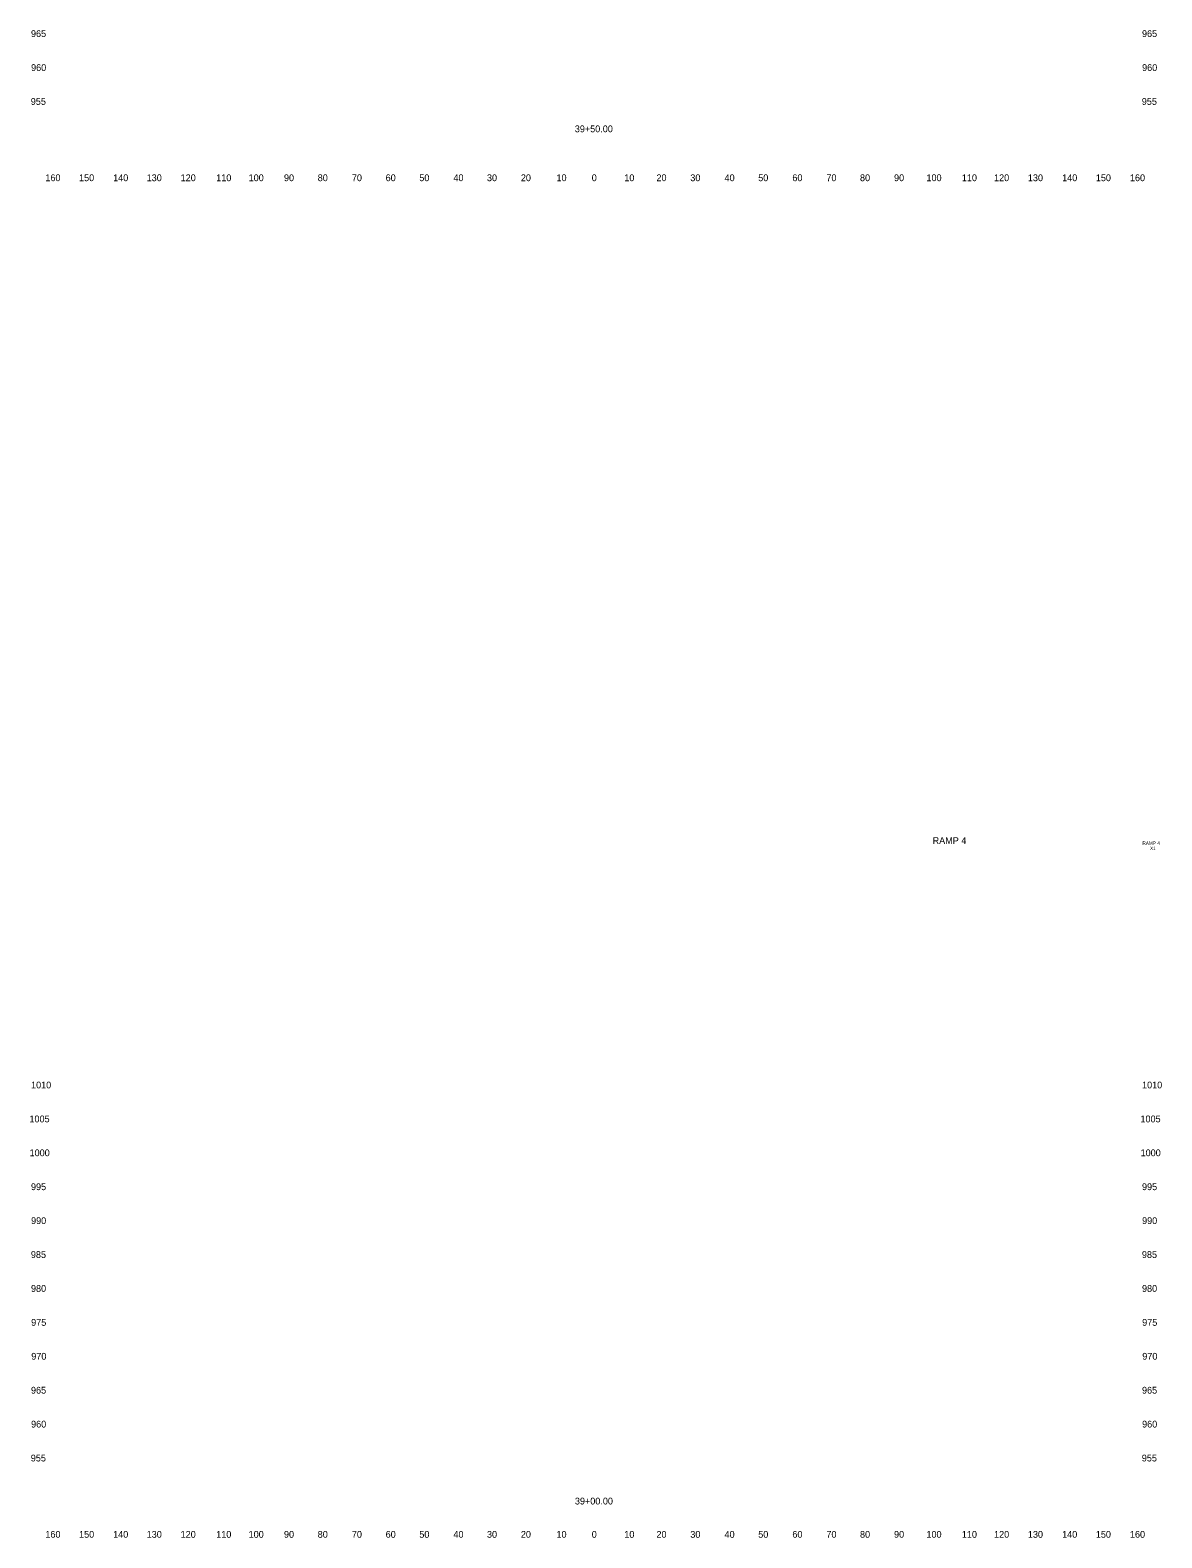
# Model space of a CAD drawing. Extents: x 4994 to 6872, y 4997 to 8804.
# Drawn here: x 4993.6 to 5327.5, y 4997.5 to 5442 of the extents above; entities that cross this region are included whole.
import ezdxf

# ---------------------------------------------------------------- set-up
doc = ezdxf.new("R2010")
doc.units = 0
for name, color, linetype in [('RD_SHT_ID', 7, 'Continuous'), ('RD_XS_TX_Offset', 7, 'Continuous'), ('RD_XS_TX_Station', 7, 'Continuous')]:
    doc.layers.add(name, color=color, linetype=linetype)

msp = doc.modelspace()

# ---------------------------------------------------------------- texts
at = {"layer": 'RD_SHT_ID'}
for s, height, p in [('RAMP 4', 2, (5259.88, 5202.06)), ('RAMP 4', 1, (5321.78, 5201.8)), ('X1', 1, (5324.02, 5200.3))]:
    msp.add_text(s, height=height, dxfattribs=at).set_placement(p)
at = {"layer": 'RD_XS_TX_Offset'}
for s, p in [('965', (4993.86, 5440)), ('965', (5321.66, 5440)), ('960', (4993.89, 5430)), ('960', (5321.69, 5430)), ('955', (4993.8, 5420)), ('955', (5321.6, 5420)), ('160', (4998.1, 5397.5)), ('150', (5008.04, 5397.5)), ('140', (5018.1, 5397.5)), ('130', (5027.99, 5397.5)), ('120', (5038.01, 5397.5)), ('110', (5048.51, 5397.5)), ('100', (5058.07, 5397.5)), ('90', (5068.5, 5397.5)), ('80', (5078.46, 5397.5)), ('70', (5088.54, 5397.5)), ('60', (5098.5, 5397.5)), ('50', (5108.43, 5397.5)), ('40', (5118.5, 5397.5)), ('30', (5128.39, 5397.5)), ('20', (5138.4, 5397.5)), ('10', (5148.91, 5397.5)), ('0', (5159.3, 5397.5)), ('0', (5159.3, 5397.5)), ('10', (5168.91, 5397.5)), ('20', (5178.4, 5397.5)), ('30', (5188.39, 5397.5)), ('40', (5198.5, 5397.5)), ('50', (5208.43, 5397.5)), ('60', (5218.5, 5397.5)), ('70', (5228.54, 5397.5)), ('80', (5238.46, 5397.5)), ('90', (5248.5, 5397.5)), ('100', (5258.07, 5397.5)), ('110', (5268.51, 5397.5)), ('120', (5278.01, 5397.5)), ('130', (5287.99, 5397.5)), ('140', (5298.1, 5397.5)), ('150', (5308.04, 5397.5)), ('160', (5318.1, 5397.5)), ('1010', (4993.88, 5130)), ('1010', (5321.68, 5130)), ('1005', (4993.4, 5120)), ('1005', (5321.2, 5120)), ('1000', (4993.44, 5110)), ('1000', (5321.24, 5110)), ('995', (4993.86, 5100)), ('995', (5321.66, 5100)), ('990', (4993.89, 5090)), ('990', (5321.69, 5090)), ('985', (4993.83, 5080)), ('985', (5321.63, 5080)), ('980', (4993.86, 5070)), ('980', (5321.66, 5070)), ('975', (4993.91, 5060)), ('975', (5321.71, 5060)), ('970', (4993.94, 5050)), ('970', (5321.74, 5050)), ('965', (4993.86, 5040)), ('965', (5321.66, 5040)), ('960', (4993.89, 5030)), ('960', (5321.69, 5030)), ('955', (4993.8, 5020)), ('955', (5321.6, 5020)), ('160', (4998.1, 4997.5)), ('150', (5008.04, 4997.5)), ('140', (5018.1, 4997.5)), ('130', (5027.99, 4997.5)), ('120', (5038.01, 4997.5)), ('110', (5048.51, 4997.5)), ('100', (5058.07, 4997.5)), ('90', (5068.5, 4997.5)), ('80', (5078.46, 4997.5)), ('70', (5088.54, 4997.5)), ('60', (5098.5, 4997.5)), ('50', (5108.43, 4997.5)), ('40', (5118.5, 4997.5)), ('30', (5128.39, 4997.5)), ('20', (5138.4, 4997.5)), ('10', (5148.91, 4997.5)), ('0', (5159.3, 4997.5)), ('0', (5159.3, 4997.5)), ('10', (5168.91, 4997.5)), ('20', (5178.4, 4997.5)), ('30', (5188.39, 4997.5)), ('40', (5198.5, 4997.5)), ('50', (5208.43, 4997.5)), ('60', (5218.5, 4997.5)), ('70', (5228.54, 4997.5)), ('80', (5238.46, 4997.5)), ('90', (5248.5, 4997.5)), ('100', (5258.07, 4997.5)), ('110', (5268.51, 4997.5)), ('120', (5278.01, 4997.5)), ('130', (5287.99, 4997.5)), ('140', (5298.1, 4997.5)), ('150', (5308.04, 4997.5)), ('160', (5318.1, 4997.5))]:
    msp.add_text(s, height=2, dxfattribs=at).set_placement(p)
at = {"layer": 'RD_XS_TX_Station'}
for s, p in [('39+50.00', (5154.31, 5411.93)), ('39+00.00', (5154.34, 5007.31))]:
    msp.add_text(s, height=2, dxfattribs=at).set_placement(p)

doc.saveas('drawing.dxf')
